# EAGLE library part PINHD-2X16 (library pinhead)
PIN HEADER
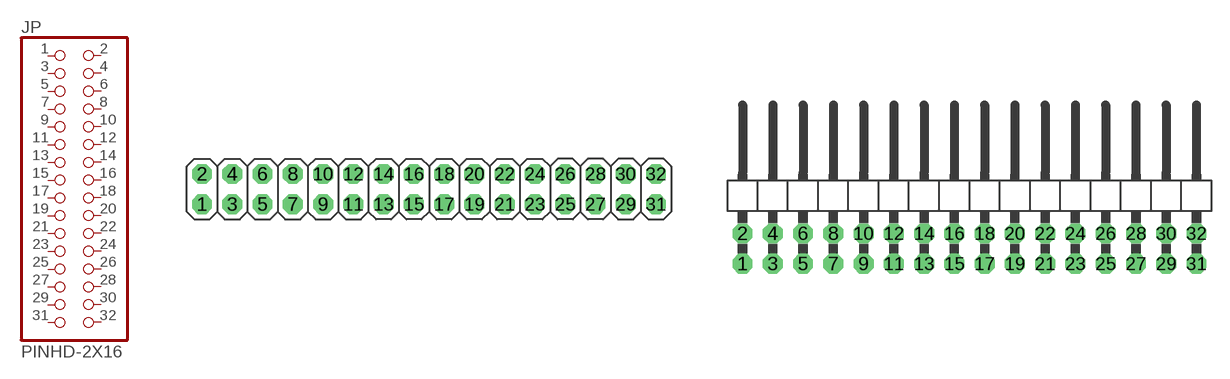
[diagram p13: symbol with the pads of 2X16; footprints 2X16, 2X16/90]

Designator prefix JP

## PINHD-2X16  [2X16]
1  1  pas
2  2  pas
3  3  pas
4  4  pas
5  5  pas
6  6  pas
7  7  pas
8  8  pas
9  9  pas
10  10  pas
11  11  pas
12  12  pas
13  13  pas
14  14  pas
15  15  pas
16  16  pas
17  17  pas
18  18  pas
19  19  pas
20  20  pas
21  21  pas
22  22  pas
23  23  pas
24  24  pas
25  25  pas
26  26  pas
27  27  pas
28  28  pas
29  29  pas
30  30  pas
31  31  pas
32  32  pas

## PINHD-2X16/90  [2X16/90]
Pads as for 2X16

## Footprint 2X16 (pad centres in mm)
PIN HEADER
drill 1.016 pad 1.67 octagon: 1 -19.05,-1.27; 2 -19.05,1.27; 3 -16.51,-1.27; 4 -16.51,1.27; 5 -13.97,-1.27; 6 -13.97,1.27; 7 -11.43,-1.27; 8 -11.43,1.27; 9 -8.89,-1.27; 10 -8.89,1.27; 11 -6.35,-1.27; 12 -6.35,1.27; 13 -3.81,-1.27; 14 -3.81,1.27; 15 -1.27,-1.27; 16 -1.27,1.27; 17 1.27,-1.27; 18 1.27,1.27; 19 3.81,-1.27; 20 3.81,1.27; 21 6.35,-1.27; 22 6.35,1.27; 23 8.89,-1.27; 24 8.89,1.27; 25 11.43,-1.27; 26 11.43,1.27; 27 13.97,-1.27; 28 13.97,1.27; 29 16.51,-1.27; 30 16.51,1.27; 31 19.05,-1.27; 32 19.05,1.27

## Footprint 2X16/90 (pad centres in mm)
PIN HEADER
drill 1.016 pad 1.67 octagon: 1 -19.05,-6.35; 2 -19.05,-3.81; 3 -16.51,-6.35; 4 -16.51,-3.81; 5 -13.97,-6.35; 6 -13.97,-3.81; 7 -11.43,-6.35; 8 -11.43,-3.81; 9 -8.89,-6.35; 10 -8.89,-3.81; 11 -6.35,-6.35; 12 -6.35,-3.81; 13 -3.81,-6.35; 14 -3.81,-3.81; 15 -1.27,-6.35; 16 -1.27,-3.81; 17 1.27,-6.35; 18 1.27,-3.81; 19 3.81,-6.35; 20 3.81,-3.81; 21 6.35,-6.35; 22 6.35,-3.81; 23 8.89,-6.35; 24 8.89,-3.81; 25 11.43,-6.35; 26 11.43,-3.81; 27 13.97,-6.35; 28 13.97,-3.81; 29 16.51,-6.35; 30 16.51,-3.81; 31 19.05,-6.35; 32 19.05,-3.81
